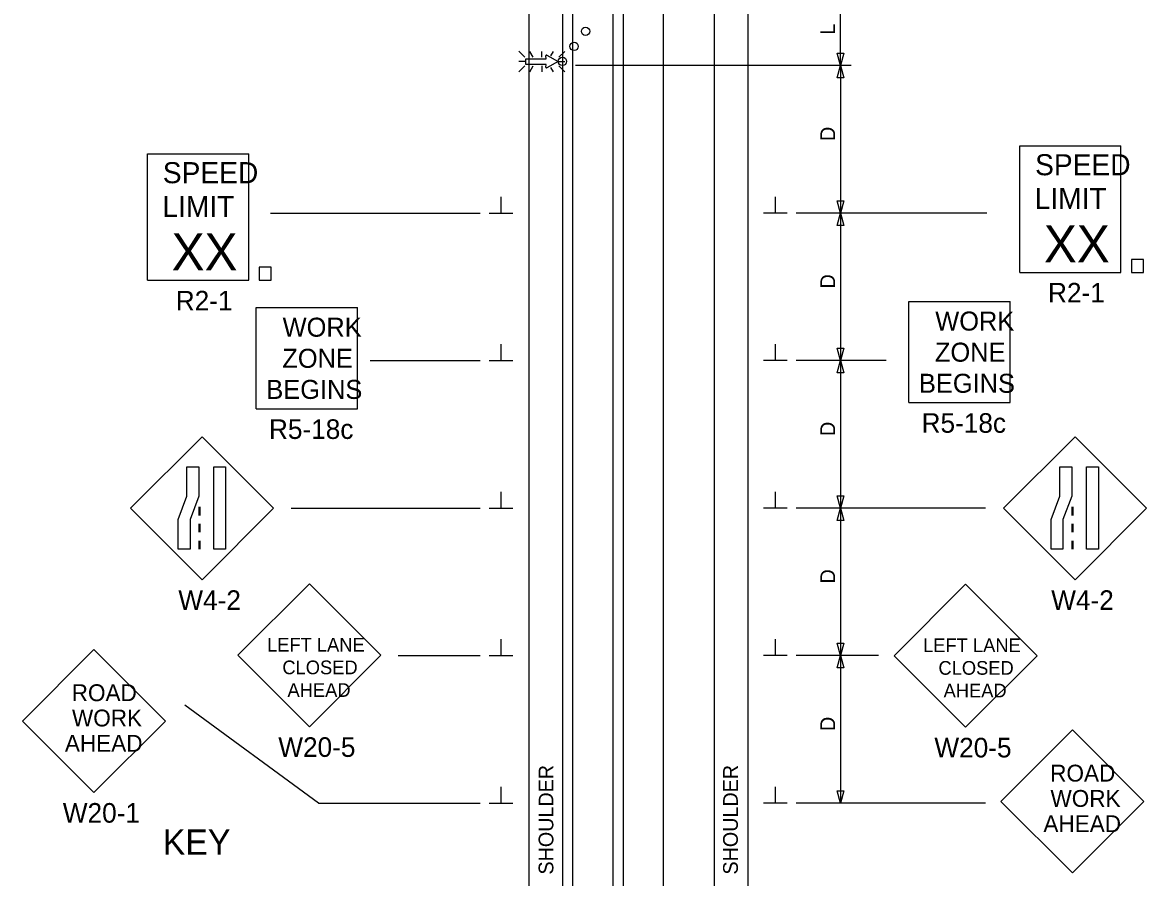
# Model space of a CAD drawing. Extents: x 16735 to 19504, y 6970 to 8243.
# Drawn here: x 16735 to 17268, y 7432 to 7838 of the extents above; entities that cross this region are included whole.
import ezdxf

# ---------------------------------------------------------------- set-up
doc = ezdxf.new("R2010")
doc.units = 0
for name, color, linetype in [('ALI_LEGAL_EX', 7, 'Continuous'), ('PAVT_EDGE_EX', 7, 'Continuous'), ('TRAFFIC_SIGNS_PR', 7, 'Continuous'), ('TYPICAL_TEXT_DIMEN_EX', 7, 'Continuous'), ('TYPICAL_TEXT_DIMEN_PR', 7, 'Continuous')]:
    doc.layers.add(name, color=color, linetype=linetype)

msp = doc.modelspace()

# ---------------------------------------------------------------- linework, layer by layer
at = {"layer": 'ALI_LEGAL_EX'}
for p, q in [((16995.95, 8243.16), (16995.95, 7425.02)), ((17019.95, 8243.16), (17019.95, 7425.02))]:
    msp.add_line(p, q, dxfattribs=at)
for points in [[(17015.15, 7783.87), (17015.15, 7758.87)], [(17039.15, 7758.87), (17039.15, 7783.87)], [(17015.15, 7683.87), (17015.15, 7658.87)], [(17039.15, 7658.87), (17039.15, 7683.87)], [(17015.15, 7583.87), (17015.15, 7558.87)], [(17039.15, 7558.87), (17039.15, 7583.87)], [(17015.15, 7483.87), (17015.15, 7458.87)], [(17039.15, 7458.87), (17039.15, 7483.87)]]:
    msp.add_lwpolyline(points, dxfattribs=at)
at = {"layer": 'PAVT_EDGE_EX'}
for p, q in [((16975.15, 8183.87), (16975.15, 7354.69)), ((16991.15, 8183.87), (16991.15, 7354.69)), ((17015.15, 8183.87), (17015.15, 7354.69)), ((17039.15, 7358.87), (17039.15, 8183.87)), ((17063.15, 8183.87), (17063.15, 7354.69)), ((17079.15, 8183.87), (17079.15, 7354.69))]:
    msp.add_line(p, q, dxfattribs=at)
at = {"layer": 'TRAFFIC_SIGNS_PR'}
for p, q in [((16973.31, 7821.47), (16970.49, 7824.29)), ((16977.26, 7821.47), (16975.64, 7824.28)), ((16981.4, 7821.47), (16981.4, 7824.28)), ((16985.58, 7822.1), (16986.84, 7824.28)), ((16992.3, 7824.28), (16989.49, 7821.47)), ((16973.31, 7819.43), (16970.49, 7819.43)), ((16989.49, 7819.43), (16992.3, 7819.43)), ((16973.31, 7817.4), (16970.49, 7814.58)), ((16975.61, 7814.58), (16977.24, 7817.4)), ((16981.4, 7817.4), (16981.4, 7814.58)), ((16986.87, 7814.58), (16985.66, 7816.67)), ((16992.3, 7814.58), (16989.49, 7817.4)), ((17208.34, 7779.4), (17256.34, 7779.4)), ((17208.34, 7719.4), (17208.34, 7779.4)), ((17256.34, 7719.4), (17256.34, 7779.4)), ((16794.2, 7775.62), (16842.2, 7775.62)), ((16794.2, 7715.62), (16794.2, 7775.62)), ((16842.2, 7715.62), (16842.2, 7775.62)), ((17208.34, 7719.4), (17256.34, 7719.4)), ((16794.2, 7715.62), (16842.2, 7715.62)), ((16845.8, 7654.65), (16845.8, 7702.65)), ((16845.8, 7702.65), (16893.8, 7702.65)), ((16893.8, 7654.65), (16893.8, 7702.65)), ((17155.65, 7657.57), (17155.65, 7705.57)), ((17155.65, 7705.57), (17203.65, 7705.57)), ((17203.65, 7657.57), (17203.65, 7705.57)), ((16845.8, 7654.65), (16893.8, 7654.65)), ((17155.65, 7657.57), (17203.65, 7657.57)), ((16820.07, 7641.39), (16786.13, 7607.45)), ((16854.01, 7607.45), (16820.07, 7641.39)), ((17234.52, 7641.39), (17200.58, 7607.45)), ((17268.46, 7607.45), (17234.52, 7641.39)), ((16786.13, 7607.45), (16820.07, 7573.51)), ((16818.51, 7608.06), (16818.51, 7604.06)), ((16819.01, 7608.06), (16819.01, 7604.06)), ((16820.07, 7573.51), (16854.01, 7607.45)), ((17200.58, 7607.45), (17234.52, 7573.51)), ((17232.96, 7608.06), (17232.96, 7604.06)), ((17233.46, 7608.06), (17233.46, 7604.06)), ((17234.52, 7573.51), (17268.46, 7607.45)), ((16818.51, 7600.06), (16818.51, 7596.06)), ((16819.01, 7600.06), (16819.01, 7596.06)), ((17232.96, 7600.06), (17232.96, 7596.06)), ((17233.46, 7600.06), (17233.46, 7596.06)), ((16818.51, 7592.06), (16818.51, 7588.06)), ((16819.01, 7592.06), (16819.01, 7588.06)), ((17232.96, 7592.06), (17232.96, 7588.06)), ((17233.46, 7592.06), (17233.46, 7588.06)), ((16871.03, 7571.64), (16837.08, 7537.7)), ((16904.97, 7537.7), (16871.03, 7571.64)), ((17182.53, 7571.39), (17148.59, 7537.45)), ((17216.47, 7537.45), (17182.53, 7571.39)), ((16768.72, 7540.44), (16734.78, 7506.49)), ((16802.66, 7506.49), (16768.72, 7540.44)), ((16837.08, 7537.7), (16871.03, 7503.76)), ((16871.03, 7503.76), (16904.97, 7537.7)), ((17148.59, 7537.45), (17182.53, 7503.51)), ((17182.53, 7503.51), (17216.47, 7537.45)), ((16734.78, 7506.49), (16768.72, 7472.55)), ((16768.72, 7472.55), (16802.66, 7506.49)), ((17233.3, 7502.28), (17199.36, 7468.33)), ((17267.24, 7468.33), (17233.3, 7502.28)), ((17199.36, 7468.33), (17233.3, 7434.39)), ((17233.3, 7434.39), (17267.24, 7468.33))]:
    msp.add_line(p, q, dxfattribs=at)
for points in [[(16983.23, 7816.75), (16983.46, 7818.05), (16973.73, 7818.05), (16973.73, 7820.79), (16983.46, 7820.79), (16983.22, 7822.09)], [(16983.73, 7822.45), (16989.04, 7819.43), (16983.73, 7816.39)]]:
    msp.add_lwpolyline(points, dxfattribs=at)
for points in [[(17261.36, 7719.4), (17266.95, 7719.4), (17266.95, 7725.57), (17261.36, 7725.57)], [(16847.22, 7715.62), (16852.81, 7715.62), (16852.81, 7721.79), (16847.22, 7721.79)], [(16818.51, 7627.12), (16818.51, 7613.14), (16814.33, 7602.04), (16814.33, 7588.06), (16808.71, 7588.06), (16808.71, 7602.04), (16812.89, 7613.14), (16812.89, 7627.12)], [(16831.18, 7627.12), (16831.18, 7588.06), (16825.56, 7588.06), (16825.56, 7627.12)], [(17232.96, 7627.12), (17232.96, 7613.14), (17228.78, 7602.04), (17228.78, 7588.06), (17223.16, 7588.06), (17223.16, 7602.04), (17227.34, 7613.14), (17227.34, 7627.12)], [(17245.63, 7627.12), (17245.63, 7588.06), (17240.01, 7588.06), (17240.01, 7627.12)]]:
    msp.add_lwpolyline(points, close=True, dxfattribs=at)
for centre in [(17002.15, 7833.78), (16996.65, 7826.65), (16991.15, 7819.53)]:
    msp.add_circle(centre, 2, dxfattribs=at)
for centre, start, end in [((16983.56, 7822.15), 61.1084, 189.2692), ((16983.56, 7816.69), 170.0407, 298.5167)]:
    msp.add_arc(centre, 0.341, start, end, dxfattribs=at)
at = {"layer": 'TYPICAL_TEXT_DIMEN_PR'}
for p, q in [((17123.15, 7817.53), (17123.15, 7848.04)), ((17123.15, 7817.53), (17121.58, 7823.39)), ((17121.58, 7823.39), (17123.15, 7823.39)), ((17123.15, 7823.39), (17124.72, 7823.39)), ((17124.72, 7823.39), (17123.15, 7817.53)), ((17128.15, 7817.53), (16997.42, 7817.53)), ((17121.58, 7811.67), (17123.15, 7817.53)), ((17123.15, 7817.53), (17123.15, 7747.53)), ((17123.15, 7817.53), (17124.72, 7811.67)), ((17123.15, 7811.67), (17121.58, 7811.67)), ((17124.72, 7811.67), (17123.15, 7811.67)), ((17123.15, 7772.4), (17123.15, 7768.63)), ((16962.03, 7747.53), (16962.03, 7755.31)), ((17092.28, 7747.53), (17092.28, 7755.31)), ((17123.15, 7747.53), (17121.58, 7753.39)), ((17121.58, 7753.39), (17123.15, 7753.39)), ((17123.15, 7753.39), (17124.72, 7753.39)), ((17124.72, 7753.39), (17123.15, 7747.53)), ((16852.6, 7747.53), (16952.15, 7747.53)), ((16956.4, 7747.53), (16967.65, 7747.53)), ((17097.9, 7747.53), (17086.65, 7747.53)), ((17192.64, 7747.53), (17102.15, 7747.53)), ((17121.58, 7741.67), (17123.15, 7747.53)), ((17123.15, 7747.53), (17123.15, 7677.53)), ((17123.15, 7747.53), (17124.72, 7741.67)), ((17123.15, 7741.67), (17121.58, 7741.67)), ((17124.72, 7741.67), (17123.15, 7741.67)), ((16962.03, 7677.53), (16962.03, 7685.31)), ((17092.28, 7677.53), (17092.28, 7685.31)), ((17123.15, 7677.53), (17121.58, 7683.39)), ((17121.58, 7683.39), (17123.15, 7683.39)), ((17123.15, 7683.39), (17124.72, 7683.39)), ((17124.72, 7683.39), (17123.15, 7677.53)), ((16899.89, 7677.53), (16952.15, 7677.53)), ((16956.4, 7677.53), (16967.65, 7677.53)), ((17097.9, 7677.53), (17086.65, 7677.53)), ((17144.8, 7677.53), (17102.15, 7677.53)), ((17121.58, 7671.67), (17123.15, 7677.53)), ((17123.15, 7677.53), (17123.15, 7607.53)), ((17123.15, 7677.53), (17124.72, 7671.67)), ((17123.15, 7671.67), (17121.58, 7671.67)), ((17124.72, 7671.67), (17123.15, 7671.67)), ((17123.15, 7632.4), (17123.15, 7628.63)), ((16962.03, 7607.53), (16962.03, 7615.31)), ((17092.28, 7607.53), (17092.28, 7615.31)), ((17123.15, 7607.53), (17121.58, 7613.39)), ((17121.58, 7613.39), (17123.15, 7613.39)), ((17123.15, 7613.39), (17124.72, 7613.39)), ((17124.72, 7613.39), (17123.15, 7607.53)), ((16862.27, 7607.53), (16952.15, 7607.53)), ((16956.4, 7607.53), (16967.65, 7607.53)), ((17097.9, 7607.53), (17086.65, 7607.53)), ((17192.04, 7607.53), (17102.15, 7607.53)), ((17121.58, 7601.67), (17123.15, 7607.53)), ((17123.15, 7607.53), (17123.15, 7537.53)), ((17123.15, 7607.53), (17124.72, 7601.67)), ((17123.15, 7601.67), (17121.58, 7601.67)), ((17124.72, 7601.67), (17123.15, 7601.67)), ((16962.03, 7537.53), (16962.03, 7545.31)), ((17092.28, 7537.53), (17092.28, 7545.31)), ((17123.15, 7537.53), (17121.58, 7543.39)), ((17121.58, 7543.39), (17123.15, 7543.39)), ((17123.15, 7543.39), (17124.72, 7543.39)), ((17124.72, 7543.39), (17123.15, 7537.53)), ((16913.15, 7537.53), (16952.15, 7537.53)), ((16956.4, 7537.53), (16967.65, 7537.53)), ((17097.9, 7537.53), (17086.65, 7537.53)), ((17141.15, 7537.53), (17102.15, 7537.53)), ((17121.58, 7531.67), (17123.15, 7537.53)), ((17123.15, 7537.53), (17123.15, 7467.53)), ((17123.15, 7537.53), (17124.72, 7531.67)), ((17123.15, 7531.67), (17121.58, 7531.67)), ((17124.72, 7531.67), (17123.15, 7531.67)), ((16875.27, 7467.53), (16811.81, 7514)), ((16962.03, 7467.53), (16962.03, 7475.31)), ((17092.28, 7467.53), (17092.28, 7475.31)), ((17123.15, 7467.53), (17121.58, 7473.39)), ((17121.58, 7473.39), (17123.15, 7473.39)), ((17123.15, 7473.39), (17124.72, 7473.39)), ((17124.72, 7473.39), (17123.15, 7467.53)), ((16875.27, 7467.53), (16952.15, 7467.53)), ((16956.4, 7467.53), (16967.65, 7467.53)), ((17097.9, 7467.53), (17086.65, 7467.53)), ((17192.04, 7467.53), (17102.15, 7467.53))]:
    msp.add_line(p, q, dxfattribs=at)

# ---------------------------------------------------------------- texts
at = {"layer": 'TRAFFIC_SIGNS_PR'}
for s, height, p in [('SPEED', 10, (16801.41, 7761.7)), ('SPEED', 10, (17215.55, 7765.48)), ('LIMIT', 10, (16801.21, 7745.7)), ('LIMIT', 10, (17215.35, 7749.48)), ('XX', 17.538, (17219.73, 7724.1)), ('XX', 17.538, (16805.59, 7720.32)), ('R2-1', 9.3, (17221.69, 7705.1)), ('R2-1', 9.3, (16807.55, 7701.32)), ('WORK', 9.021, (16858.3, 7688.86)), ('WORK', 9.021, (17168.15, 7691.77)), ('ZONE', 9.021, (17168, 7677.01)), ('ZONE', 9.021, (16858.15, 7674.1)), ('BEGINS', 9.021, (17160.41, 7662.25)), ('BEGINS', 9.021, (16850.56, 7659.34)), ('R5-18c', 9.3, (16851.81, 7640.35)), ('R5-18c', 9.3, (17161.66, 7643.27)), ('W4-2', 9.3, (16808.77, 7559.21)), ('W4-2', 9.3, (17223.21, 7559.21)), ('LEFT LANE', 6.5, (16850.88, 7539.44)), ('LEFT LANE', 6.5, (17162.38, 7539.19)), ('CLOSED', 6.5, (16858.17, 7528.69)), ('CLOSED', 6.5, (17169.67, 7528.44)), ('ROAD', 8, (16758.15, 7515.91)), ('AHEAD', 6.5, (16860.6, 7517.94)), ('AHEAD', 6.5, (17172.11, 7517.69)), ('WORK', 8, (16758.28, 7503.91)), ('AHEAD', 8, (16754.92, 7491.91)), ('W20-5', 9.3, (16856.24, 7489.46)), ('W20-5', 9.3, (17167.75, 7489.21)), ('ROAD', 8, (17222.72, 7477.75)), ('WORK', 8, (17222.86, 7465.75)), ('W20-1', 9.3, (16753.93, 7458.25)), ('AHEAD', 8, (17219.5, 7453.75))]:
    msp.add_text(s, height=height, dxfattribs=at).set_placement(p)
at = {"layer": 'TYPICAL_TEXT_DIMEN_EX'}
msp.add_text('KEY', height=12, dxfattribs=at).set_placement((16801.4, 7443.01))
at = {"layer": 'TYPICAL_TEXT_DIMEN_PR'}
for s, p in [('L', (17120.59, 7832.14)), ('D', (17120.59, 7781.75)), ('D', (17120.59, 7711.75)), ('D', (17120.59, 7641.75)), ('D', (17120.59, 7571.75)), ('D', (17120.59, 7501.75)), ('SHOULDER', (16986.84, 7433.62)), ('SHOULDER', (17074.43, 7433.62))]:
    msp.add_text(s, height=7, rotation=90, dxfattribs=at).set_placement(p)

doc.saveas('drawing.dxf')
